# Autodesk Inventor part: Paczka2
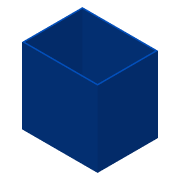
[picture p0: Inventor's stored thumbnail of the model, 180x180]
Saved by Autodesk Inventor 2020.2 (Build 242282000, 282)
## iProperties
Created: 2006-01
Part Number: Paczka2
Document SubType Name: Modeling
Designer: F.Stasiak
Density: 1 g/cm^3
Material: Ogólny
Appearance: Niebieski morski
Manager: www.cadconsulting.pl
Company: Fabian Stasiak CAD Consulting
Author: F.Stasiak
Subject: Zbiór ćwiczeń. Autodesk Inventor 2020. Kurs podstawowy
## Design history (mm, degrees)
sketch "Szkic1"
  geometry: L1 (310.679, 424.295)-(1310.679, 424.295); L2 (1310.679, 424.295)-(1310.679, -375.705); L3 (1310.679, -375.705)-(310.679, -375.705); L4 (310.679, -375.705)-(310.679, 424.295)
  constraints: 8 end point, 2 parallel, 1 horizontal, 1 perpendicular
  dimensions: "d0" = 1000 distance of L2.end L3.end; "d1" = 800 distance of L3.end L1.start
extrude "Wyciągnięcie proste1" new body sketch "Szkic1" distance "d2" = 1000; taper "d3" = 0 deg
feature "Skorupa1" dims "d4" = 20
node "Bryła1"
node "Korpusy bryłowe"
node "Korpusy powierzchniowe"
